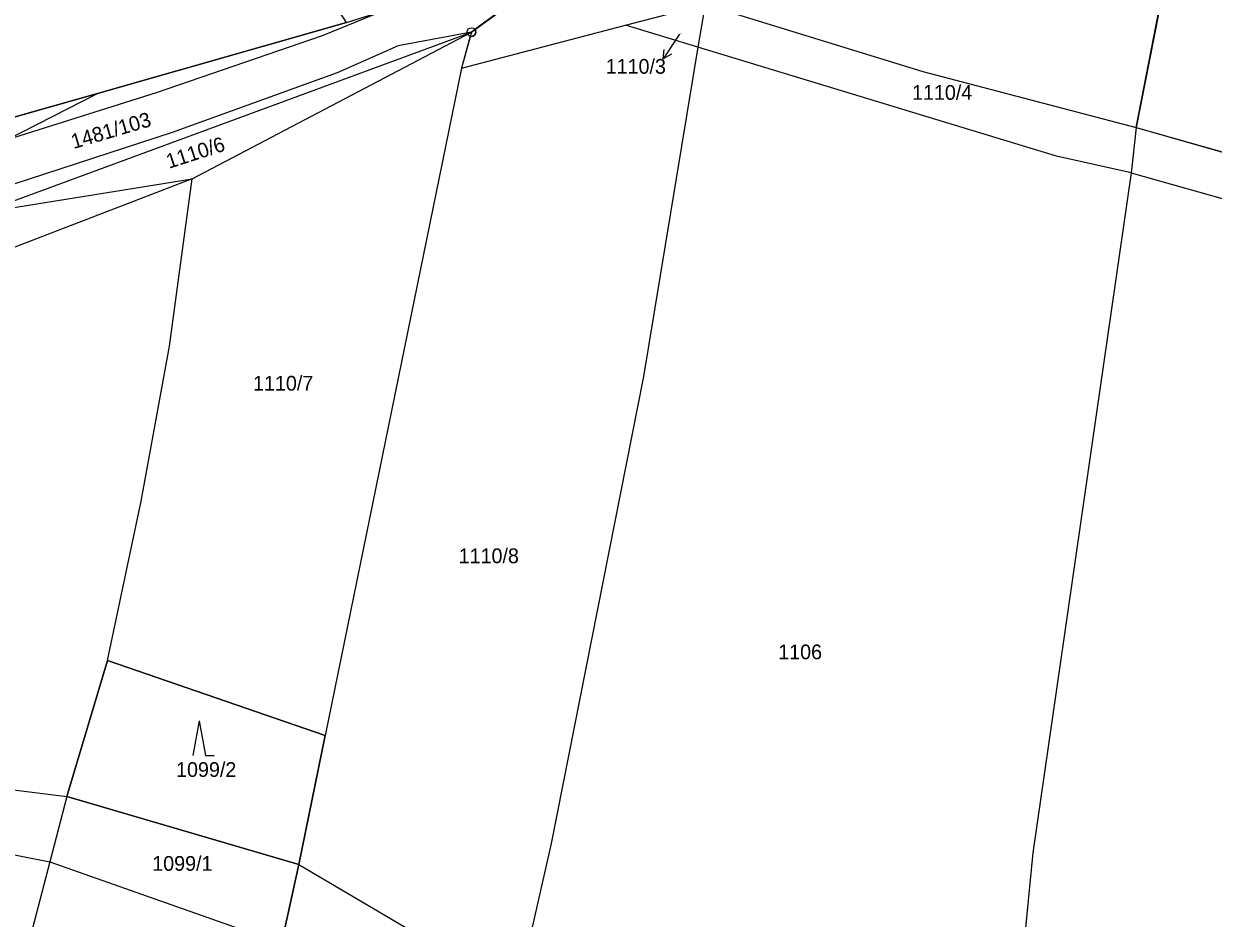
# Model space of a CAD drawing. Extents: x -760642 to -757221, y -1092371 to -1088855.
# Drawn here: x -759415.4 to -759278.1, y -1089962.1 to -1089858.9 of the extents above; entities that cross this region are included whole.
import ezdxf

# ---------------------------------------------------------------- set-up
doc = ezdxf.new("R2010")
doc.units = 0
for name, color, linetype in [('Vrstva 1', 7, 'Continuous'), ('Vrstva 16', 7, 'Continuous'), ('Vrstva 18', 7, 'Continuous'), ('Vrstva 24', 7, 'Continuous'), ('Vrstva 25', 7, 'Continuous'), ('Vrstva 26', 7, 'Continuous'), ('Vrstva 27', 7, 'Continuous'), ('Vrstva 30', 7, 'Continuous'), ('Vrstva 4', 7, 'Continuous')]:
    doc.layers.add(name, color=color, linetype=linetype)

msp = doc.modelspace()

# ---------------------------------------------------------------- linework, layer by layer
at = {"layer": 'Vrstva 1'}
for p, q in [((-759363.71, -1089859.84), (-759349.81, -1089849.6)), ((-759286.99, -1089870.84), (-759283.89, -1089854.99)), ((-759345.92, -1089859.05), (-759336.74, -1089856.65)), ((-759336.74, -1089856.65), (-759337.59, -1089861.58)), ((-759336.74, -1089856.65), (-759311.61, -1089864.4)), ((-759378.14, -1089858.72), (-759406.87, -1089866.92)), ((-759420.17, -1089880.68), (-759363.71, -1089859.84)), ((-759395.92, -1089876.8), (-759363.71, -1089859.84)), ((-759364.85, -1089864), (-759345.92, -1089859.05)), ((-759363.71, -1089859.84), (-759364.85, -1089864)), ((-759337.59, -1089861.58), (-759345.92, -1089859.05)), ((-759337.59, -1089861.58), (-759343.85, -1089899.61)), ((-759296.19, -1089874.15), (-759337.59, -1089861.58)), ((-759364.85, -1089864), (-759380.58, -1089941.06)), ((-759311.61, -1089864.4), (-759286.99, -1089870.84)), ((-759406.87, -1089866.92), (-759426.55, -1089872.5)), ((-759417.26, -1089872.25), (-759406.87, -1089866.92)), ((-759286.99, -1089870.84), (-759287.57, -1089876.11)), ((-759286.99, -1089870.84), (-759236.1, -1089885.41)), ((-759287.57, -1089876.11), (-759296.19, -1089874.15)), ((-759395.92, -1089876.8), (-759449.34, -1089897.34)), ((-759420.17, -1089880.68), (-759395.92, -1089876.8)), ((-759398.53, -1089896.09), (-759395.92, -1089876.8)), ((-759287.57, -1089876.11), (-759298.92, -1089954.6)), ((-759287.57, -1089876.11), (-759237.54, -1089890.17)), ((-759401.83, -1089913.99), (-759398.53, -1089896.09)), ((-759343.85, -1089899.61), (-759354.52, -1089953.51)), ((-759405.71, -1089932.37), (-759401.83, -1089913.99)), ((-759410.39, -1089948.09), (-759405.71, -1089932.37)), ((-759405.71, -1089932.37), (-759380.58, -1089941.06)), ((-759380.58, -1089941.06), (-759383.62, -1089955.93)), ((-759459.18, -1089942.03), (-759410.39, -1089948.09)), ((-759460.03, -1089946.19), (-759412.35, -1089955.63)), ((-759410.39, -1089948.09), (-759412.35, -1089955.63)), ((-759410.39, -1089948.09), (-759383.62, -1089955.93)), ((-759354.52, -1089953.51), (-759358.4, -1089970.79)), ((-759298.92, -1089954.6), (-759301.67, -1089982.28)), ((-759412.35, -1089955.63), (-759422.87, -1089995.75)), ((-759412.35, -1089955.63), (-759385.61, -1089965.07)), ((-759383.62, -1089955.93), (-759385.61, -1089965.07)), ((-759383.62, -1089955.93), (-759358.4, -1089970.79))]:
    msp.add_line(p, q, dxfattribs=at)
at = {"layer": 'Vrstva 16'}
for p, q in [((-759339.69, -1089860.07), (-759339.93, -1089860.44)), ((-759339.93, -1089860.44), (-759341.576, -1089862.948))]:
    msp.add_line(p, q, dxfattribs=at)
msp.add_lwpolyline([(-759340.609, -1089862.386), (-759341.576, -1089862.948), (-759341.445, -1089861.838)], dxfattribs=at)
at = {"layer": 'Vrstva 24'}
for radius in [0.5, 0.0327]:
    msp.add_circle((-759363.71, -1089859.84), radius, dxfattribs=at)
at = {"layer": 'Vrstva 25'}
for p, q in [((-759395.132, -1089939.339), (-759395.865, -1089943.339)), ((-759395.132, -1089939.339), (-759394.399, -1089943.339)), ((-759394.399, -1089943.339), (-759393.399, -1089943.339))]:
    msp.add_line(p, q, dxfattribs=at)
at = {"layer": 'Vrstva 26'}
for points in [[(-759317.37, -1089833.6), (-759323.6, -1089824.23), (-759334.06, -1089838.74), (-759335.42, -1089839.71), (-759335.63, -1089846.73), (-759336.74, -1089856.65), (-759311.61, -1089864.4), (-759286.99, -1089870.84), (-759283.89, -1089854.99), (-759303.82, -1089850.54), (-759304.85, -1089853.03), (-759313.99, -1089849.22), (-759312.69, -1089846.08), (-759318.61, -1089843.62), (-759320.15, -1089847.31), (-759323.57, -1089845.89), (-759322.03, -1089842.19), (-759327.38, -1089839.96), (-759324.81, -1089833.78), (-759318.64, -1089836.35), (-759317.37, -1089833.6)], [(-759363.842, -1089860.322), (-759364.85, -1089864), (-759345.92, -1089859.05), (-759336.74, -1089856.65), (-759335.63, -1089846.73), (-759335.42, -1089839.71), (-759349.81, -1089849.6), (-759363.307, -1089859.543)], [(-759378.14, -1089858.72), (-759386.35, -1089845.99), (-759403.24, -1089848.8), (-759428.52, -1089847.55), (-759426.55, -1089872.5), (-759406.87, -1089866.92), (-759378.14, -1089858.72)], [(-759283.89, -1089854.99), (-759286.99, -1089870.84), (-759236.1, -1089885.41), (-759233.18, -1089868.87), (-759233.14, -1089867.25), (-759235.54, -1089866.4), (-759248.15, -1089861.95), (-759265.97, -1089851.91), (-759281.18, -1089847.83), (-759281.19, -1089846.87), (-759282.01, -1089845.41), (-759283.89, -1089854.99)]]:
    msp.add_lwpolyline(points, dxfattribs=at)
for start, end in [(254.67498, 0), (0, 36.37873)]:
    msp.add_arc((-759363.71, -1089859.84), 0.5, start, end, dxfattribs=at)
at = {"layer": 'Vrstva 27'}
msp.add_lwpolyline([(-759426.55, -1089872.5), (-759406.87, -1089866.92), (-759378.14, -1089858.72), (-759374.18, -1089857.5), (-759364.43, -1089851.2), (-759353.63, -1089844.23), (-759353.09, -1089845.07), (-759339.09, -1089836.39), (-759338.42, -1089835.66), (-759335.42, -1089839.71), (-759363.71, -1089859.84), (-759364.85, -1089864), (-759345.92, -1089859.05), (-759336.74, -1089856.65), (-759311.61, -1089864.4), (-759286.99, -1089870.84), (-759236.1, -1089885.41)], dxfattribs=at)
at = {"layer": 'Vrstva 30'}
for points in [[(-759410.39, -1089948.09), (-759383.62, -1089955.93), (-759380.58, -1089941.06), (-759405.71, -1089932.37), (-759410.39, -1089948.09)], [(-759412.35, -1089955.63), (-759385.61, -1089965.07), (-759383.62, -1089955.93), (-759410.39, -1089948.09), (-759412.35, -1089955.63)]]:
    msp.add_lwpolyline(points, dxfattribs=at)
at = {"layer": 'Vrstva 4'}
for p, q in [((-759380.89, -1089860.24), (-759374.18, -1089857.5)), ((-759400.03, -1089866.83), (-759380.89, -1089860.24)), ((-759363.71, -1089859.84), (-759372.17, -1089861.44)), ((-759372.17, -1089861.44), (-759379.21, -1089864.55)), ((-759379.21, -1089864.55), (-759398.23, -1089871.43)), ((-759417.26, -1089872.25), (-759400.03, -1089866.83)), ((-759398.23, -1089871.43), (-759425.35, -1089880.28))]:
    msp.add_line(p, q, dxfattribs=at)

# ---------------------------------------------------------------- texts
at = {"layer": 'Vrstva 16'}
msp.add_text('1110/3', height=1.7, dxfattribs=at).set_placement((-759348.213, -1089864.65))
at = {"layer": 'Vrstva 18'}
for s, height, p in [('1110/3', 0.1, (-759339.821, -1089860.07)), ('1110/4', 1.7, (-759312.86, -1089867.66)), ('1110/7', 1.7, (-759388.91, -1089901.23)), ('1110/8', 1.7, (-759365.18, -1089921.15)), ('1106', 1.7, (-759328.3, -1089932.24)), ('1099/2', 1.7, (-759397.79, -1089945.82)), ('1099/1', 1.7, (-759400.54, -1089956.66))]:
    msp.add_text(s, height=height, dxfattribs=at).set_placement(p)
for s, rotation, p in [('1481/103', 16.45524, (-759409.62, -1089873.35)), ('1110/6', 17.89272, (-759398.61, -1089875.63))]:
    msp.add_text(s, height=1.7, rotation=rotation, dxfattribs=at).set_placement(p)

doc.saveas('drawing.dxf')
